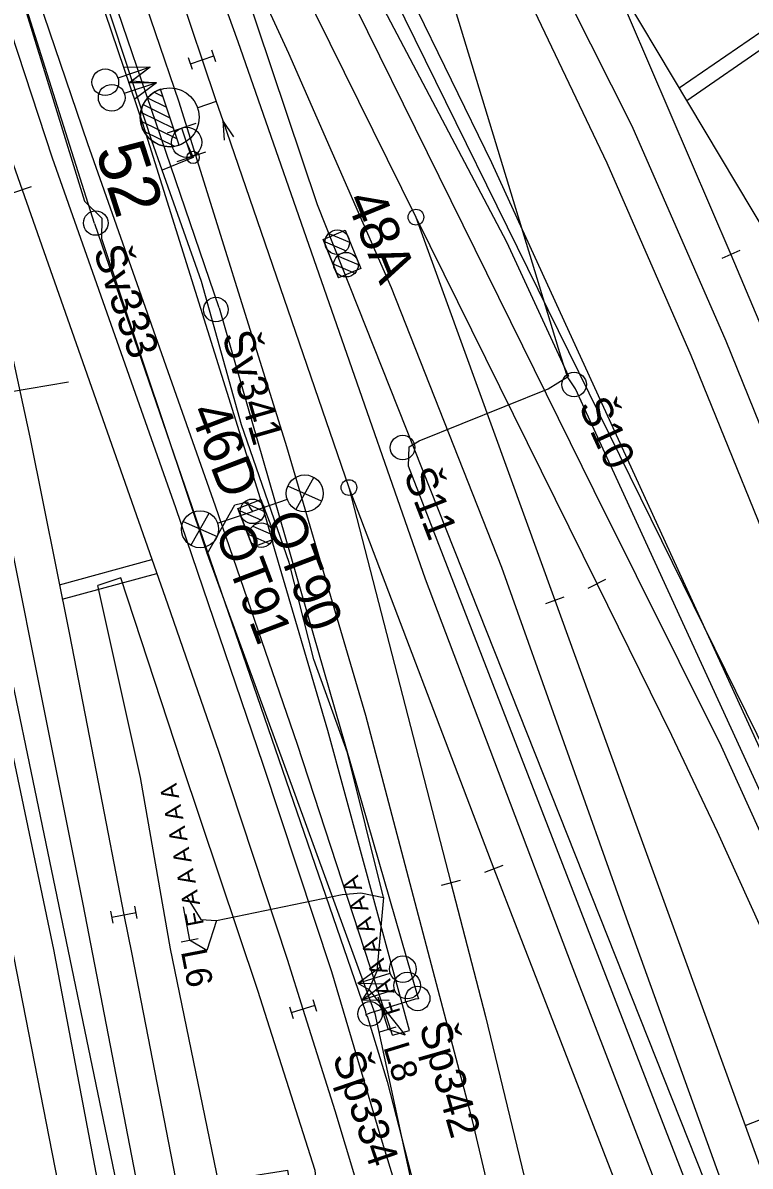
# Model space of a CAD drawing. Extents: x -545736 to -544888, y -1122892 to -1119128.
# Drawn here: x -545209.03 to -545179.41, y -1121691.68 to -1121645.11 of the extents above; entities that cross this region are included whole.
import ezdxf

# ---------------------------------------------------------------- set-up
doc = ezdxf.new("R2010")
doc.units = 0
for name, color, linetype in [('osvětlené plochy-hodnota-obrys', 7, 'Continuous'), ('Vrstva 1 - Koleje', 7, 'Continuous'), ('Vrstva 11 - Trakce', 7, 'Continuous'), ('Vrstva 12 - Trakce zaklady', 7, 'Continuous'), ('Vrstva 2 - Vyhybky', 7, 'Continuous'), ('Vrstva 25', 7, 'Continuous'), ('Vrstva 26', 7, 'Continuous'), ('Vrstva 27', 7, 'Continuous'), ('Vrstva 28 - zabzar', 7, 'Continuous'), ('Vrstva 3 - Lisy - Pocitaci body', 7, 'Continuous'), ('Vrstva 35', 7, 'Continuous'), ('Vrstva 4 - Teren - stezky - prechody - plochy', 7, 'Continuous'), ('Vrstva 43', 7, 'Continuous'), ('Vrstva 44', 7, 'Continuous'), ('Vrstva 6 - Navesti', 7, 'Continuous'), ('Vrstva 7', 7, 'Continuous'), ('Vrstva 7 - Namezniky-vystroj', 7, 'Continuous')]:
    doc.layers.add(name, color=color, linetype=linetype)

msp = doc.modelspace()

# ---------------------------------------------------------------- linework, layer by layer
at = {"layer": 'osvětlené plochy-hodnota-obrys'}
for points in [[(-545137.864, -1121889.42), (-545168.59, -1121731.992), (-545178.308, -1121699.721), (-545197.027, -1121652.528), (-545208.16, -1121619.35), (-545217.952, -1121591.114), (-545225.649, -1121565.547)], [(-545115.194, -1122188.84), (-545115.464, -1122158.52), (-545110.116, -1122078.531), (-545109.516, -1122044.98), (-545111.654, -1121993.485), (-545115.876, -1121955.778), (-545121.955, -1121920.051), (-545160.528, -1121723.806), (-545171.589, -1121690.909), (-545189.933, -1121650.816), (-545214.916, -1121599.46)]]:
    msp.add_lwpolyline(points, dxfattribs=at)
at = {"layer": 'Vrstva 1 - Koleje'}
for points in [[(-545220.059, -1121592.227), (-545219.8, -1121592.995), (-545214.751, -1121607.971), (-545209.438, -1121623.729), (-545206.712, -1121631.824), (-545204.285, -1121639.023), (-545202.147, -1121645.365), (-545201.724, -1121646.618), (-545201.151, -1121648.315)], [(-545225.616, -1121618.075), (-545225.108, -1121619.818), (-545223.546, -1121625.178), (-545221.373, -1121632.649), (-545218.975, -1121641.029), (-545216.466, -1121650.504), (-545215.616, -1121653.926), (-545213.339, -1121663.68), (-545211.292, -1121673.464), (-545209.393, -1121683.199), (-545207.488, -1121692.987)], [(-545219.417, -1121620.337), (-545219.184, -1121621.102), (-545214.573, -1121636.23), (-545210.836, -1121652.388), (-545208.739, -1121661.984), (-545207.134, -1121670.028), (-545205.963, -1121676.033), (-545204.911, -1121681.437), (-545204.598, -1121683.045), (-545202.446, -1121694.084)], [(-545219.417, -1121620.337), (-545219.184, -1121621.102), (-545214.573, -1121636.23), (-545209.054, -1121651.908), (-545206.51, -1121659.176), (-545203.144, -1121668.78), (-545201.044, -1121674.823), (-545198.261, -1121683.246), (-545197.623, -1121685.281), (-545196.328, -1121689.408), (-545194.686, -1121694.87)], [(-545191.612, -1121632.129), (-545190.978, -1121633.194), (-545185.162, -1121642.962), (-545180.201, -1121654.544), (-545176.154, -1121664.128), (-545173.907, -1121669.92), (-545171.157, -1121677.438)], [(-545191.612, -1121632.129), (-545190.978, -1121633.194), (-545185.162, -1121642.962), (-545178.685, -1121653.839)], [(-545200.377, -1121638.127), (-545200.027, -1121638.835), (-545193.022, -1121653.026), (-545187.361, -1121668.627), (-545185.993, -1121672.41), (-545184.116, -1121677.602), (-545182.386, -1121682.379), (-545180.136, -1121688.593), (-545177.412, -1121696.104), (-545175.179, -1121702.365), (-545173.107, -1121708.51), (-545170.943, -1121715.381), (-545168.904, -1121722.322), (-545166.838, -1121730.016), (-545165.721, -1121734.52), (-545165.378, -1121735.902), (-545163.622, -1121743.653), (-545162.109, -1121751.114), (-545160.876, -1121757.439), (-545159.51, -1121764.477), (-545158.293, -1121770.72), (-545156.873, -1121778.046)], [(-545200.377, -1121638.127), (-545200.027, -1121638.835), (-545193.022, -1121653.026), (-545185.653, -1121667.954), (-545182.618, -1121674.124), (-545180.75, -1121678.05), (-545177.273, -1121685.741), (-545175.056, -1121690.975), (-545171.981, -1121698.73), (-545169.454, -1121705.612), (-545167.151, -1121712.394), (-545165.943, -1121716.253), (-545164.96, -1121719.394), (-545162.82, -1121726.889), (-545161.406, -1121732.291), (-545159.388, -1121740.831), (-545157.763, -1121748.706), (-545156.207, -1121756.669), (-545155.623, -1121759.664)], [(-545201.151, -1121648.315), (-545200.885, -1121649.09), (-545195.75, -1121664.039), (-545189.847, -1121679.563), (-545187.972, -1121684.404), (-545185.383, -1121691.101), (-545182.479, -1121698.59)], [(-545201.151, -1121648.315), (-545200.885, -1121649.09), (-545195.75, -1121664.039), (-545191.597, -1121680.133), (-545190.187, -1121685.59), (-545187.923, -1121694.959)]]:
    msp.add_lwpolyline(points, dxfattribs=at)
at = {"layer": 'Vrstva 11 - Trakce'}
for p, q in [((-545196.569, -1121653.691), (-545195.727, -1121654.045)), ((-545196.721, -1121654.033), (-545195.868, -1121654.393)), ((-545196.214, -1121654.605), (-545195.372, -1121654.959)), ((-545196.366, -1121654.947), (-545195.513, -1121655.307)), ((-545200.019, -1121664.643), (-545199.184, -1121665.016)), ((-545200.178, -1121664.982), (-545199.332, -1121665.36)), ((-545199.663, -1121665.612), (-545198.828, -1121665.985)), ((-545199.822, -1121665.951), (-545198.976, -1121666.329))]:
    msp.add_line(p, q, dxfattribs=at)
msp.add_lwpolyline([(-545232.384, -1121664.189), (-545218.403, -1121661.636), (-545207.172, -1121659.74)], dxfattribs=at)
for centre in [(-545196.225, -1121654.048), (-545195.87, -1121654.962), (-545199.682, -1121665.008), (-545199.326, -1121665.977)]:
    msp.add_circle(centre, 0.5, dxfattribs=at)
at = {"layer": 'Vrstva 12 - Trakce zaklady'}
for p, q in [((-545196.805, -1121653.935), (-545195.901, -1121653.556)), ((-545195.267, -1121655.112), (-545196.172, -1121655.494)), ((-545200.274, -1121664.888), (-545199.34, -1121664.531)), ((-545198.734, -1121666.116), (-545199.668, -1121666.473))]:
    msp.add_line(p, q, dxfattribs=at)
for points in [[(-545196.172, -1121655.494), (-545196.805, -1121653.935), (-545195.901, -1121653.556), (-545195.267, -1121655.112), (-545196.172, -1121655.494)], [(-545195.901, -1121653.556), (-545195.901, -1121653.556), (-545195.267, -1121655.112), (-545195.267, -1121655.112)], [(-545196.805, -1121653.935), (-545196.805, -1121653.935), (-545196.172, -1121655.494), (-545196.172, -1121655.494)], [(-545199.668, -1121666.473), (-545200.274, -1121664.888), (-545199.34, -1121664.531), (-545198.734, -1121666.116), (-545199.668, -1121666.473)], [(-545200.274, -1121664.888), (-545200.274, -1121664.888), (-545199.668, -1121666.473), (-545199.668, -1121666.473)], [(-545199.34, -1121664.531), (-545199.34, -1121664.531), (-545198.734, -1121666.116), (-545198.734, -1121666.116)]]:
    msp.add_lwpolyline(points, dxfattribs=at)
at = {"layer": 'Vrstva 2 - Vyhybky'}
for p, q in [((-545203.948, -1121648.167), (-545203.184, -1121648.545)), ((-545203.683, -1121647.941), (-545203.329, -1121648.117)), ((-545202.662, -1121650.092), (-545203.43, -1121647.818)), ((-545204.125, -1121648.437), (-545203.039, -1121648.974)), ((-545201.151, -1121648.315), (-545201.909, -1121648.571)), ((-545204.235, -1121649.097), (-545202.75, -1121649.832)), ((-545204.225, -1121648.745), (-545202.894, -1121649.403)), ((-545204.103, -1121649.519), (-545202.855, -1121650.137)), ((-545209.432, -1121652.04), (-545208.676, -1121651.776)), ((-545179.835, -1121654.384), (-545180.567, -1121654.704)), ((-545186.012, -1121668.131), (-545185.294, -1121667.777)), ((-545187.737, -1121668.763), (-545186.985, -1121668.491)), ((-545190.22, -1121679.707), (-545189.474, -1121679.419)), ((-545191.983, -1121680.238), (-545191.211, -1121680.028))]:
    msp.add_line(p, q, dxfattribs=at)
for points in [[(-545191.612, -1121632.129), (-545190.978, -1121633.194), (-545185.162, -1121642.962), (-545178.685, -1121653.839)], [(-545200.377, -1121638.127), (-545200.027, -1121638.835), (-545193.022, -1121653.026), (-545185.653, -1121667.954)], [(-545185.162, -1121642.962), (-545180.201, -1121654.544)], [(-545201.151, -1121648.315), (-545200.885, -1121649.09), (-545195.75, -1121664.039), (-545189.847, -1121679.563)], [(-545200.438, -1121649.754), (-545200.885, -1121649.09), (-545200.83, -1121649.888)], [(-545193.022, -1121653.026), (-545187.361, -1121668.627)], [(-545195.75, -1121664.039), (-545191.597, -1121680.133)]]:
    msp.add_lwpolyline(points, dxfattribs=at)
for centre, radius in [((-545203.046, -1121648.955), 1.2), ((-545193.022, -1121653.026), 0.32), ((-545195.75, -1121664.039), 0.32)]:
    msp.add_circle(centre, radius, dxfattribs=at)
msp.add_arc((-545203.046, -1121648.955), 1.2, 108.6561, 288.6561, dxfattribs=at)
at = {"layer": 'Vrstva 25'}
for p, q in [((-545196.862, -1121664.588), (-545198.243, -1121663.981)), ((-545197.177, -1121663.623), (-545197.916, -1121664.937)), ((-545198.263, -1121664.521), (-545199.682, -1121665.008)), ((-545202.502, -1121665.428), (-545201.121, -1121666.035)), ((-545202.187, -1121666.393), (-545201.448, -1121665.079)), ((-545201.101, -1121665.495), (-545199.682, -1121665.008))]:
    msp.add_line(p, q, dxfattribs=at)
for centre in [(-545197.549, -1121664.278), (-545201.815, -1121665.738)]:
    msp.add_circle(centre, 0.754, dxfattribs=at)
at = {"layer": 'Vrstva 26'}
for points in [[(-545210.933, -1121634.824), (-545211.323, -1121634.442), (-545211.443, -1121634.176), (-545211.731, -1121634.255), (-545211.919, -1121635.114), (-545211.957, -1121635.419), (-545209.781, -1121641.802), (-545206.521, -1121652.377), (-545205.807, -1121653.061), (-545205.829, -1121653.898), (-545201.519, -1121666.737), (-545200.402, -1121664.748), (-545199.878, -1121664.619), (-545199.803, -1121664.841), (-545199.682, -1121665.008)], [(-545201.519, -1121666.737), (-545194.694, -1121685.456), (-545192.548, -1121695.403), (-545191.089, -1121700.472), (-545190.706, -1121700.096), (-545190.052, -1121700.262)]]:
    msp.add_lwpolyline(points, dxfattribs=at)
at = {"layer": 'Vrstva 27'}
msp.add_line((-545202.092, -1121650.614), (-545202.108, -1121650.566), dxfattribs=at)
msp.add_circle((-545202.1, -1121650.59), 0.25, dxfattribs=at)
at = {"layer": 'Vrstva 28 - zabzar'}
for points in [[(-545194.35, -1121680.74), (-545195.81, -1121674.84), (-545197.18, -1121671.04), (-545198.18, -1121667.09), (-545200.12, -1121661.49), (-545201.75, -1121655.65), (-545203.36, -1121651.11), (-545203.78, -1121649.92), (-545204.58, -1121647.47), (-545205.65, -1121644.21), (-545208.01, -1121637.17), (-545208.1, -1121636.42)], [(-545203.85, -1121646.92), (-545204.58, -1121647.47), (-545203.59, -1121647.55)], [(-545202.36, -1121649.98), (-545202.1, -1121650.59), (-545203.36, -1121651.11)], [(-545202.36, -1121680.69), (-545201.78, -1121681.63), (-545201.15, -1121681.67), (-545201.54, -1121682.9), (-545202.24, -1121682.47)], [(-545201.15, -1121681.67), (-545196.02, -1121680.62), (-545195.27, -1121680.54), (-545194.35, -1121680.74)], [(-545194.35, -1121680.74), (-545194.61, -1121683.74), (-545194.94, -1121684.49), (-545193.46, -1121686.35), (-545194.16, -1121686.11)], [(-545195.39, -1121684.23), (-545194.94, -1121684.49), (-545195.21, -1121684.9)]]:
    msp.add_lwpolyline(points, dxfattribs=at)
at = {"layer": 'Vrstva 3 - Lisy - Pocitaci body'}
for p, q in [((-545201.17, -1121646.695), (-545201.33, -1121646.221)), ((-545202.118, -1121647.015), (-545202.278, -1121646.541)), ((-545202.198, -1121646.778), (-545201.25, -1121646.458)), ((-545203.85, -1121646.92), (-545205.158, -1121647.361)), ((-545203.85, -1121646.92), (-545204.941, -1121646.924)), ((-545203.85, -1121646.92), (-545204.721, -1121647.578)), ((-545203.59, -1121647.55), (-545204.898, -1121647.991)), ((-545203.59, -1121647.55), (-545204.681, -1121647.554)), ((-545203.59, -1121647.55), (-545204.461, -1121648.208)), ((-545203.141, -1121649.594), (-545201.974, -1121649.199)), ((-545202.162, -1121650.563), (-545202.558, -1121649.397)), ((-545202.746, -1121650.761), (-545201.579, -1121650.366)), ((-545204.372, -1121681.587), (-545204.468, -1121681.096)), ((-545205.354, -1121681.778), (-545205.45, -1121681.287)), ((-545205.402, -1121681.533), (-545204.42, -1121681.341)), ((-545195.39, -1121684.23), (-545194.507, -1121683.59)), ((-545195.39, -1121684.23), (-545194.074, -1121683.815)), ((-545195.39, -1121684.23), (-545194.299, -1121684.248)), ((-545195.21, -1121684.9), (-545194.327, -1121684.26)), ((-545195.21, -1121684.9), (-545193.894, -1121684.485)), ((-545197.221, -1121684.893), (-545197.071, -1121685.37)), ((-545195.21, -1121684.9), (-545194.119, -1121684.918)), ((-545198.175, -1121685.192), (-545198.025, -1121685.669)), ((-545197.146, -1121685.131), (-545198.1, -1121685.431))]:
    msp.add_line(p, q, dxfattribs=at)
for centre, radius in [((-545205.672, -1121647.532), 0.542), ((-545205.412, -1121648.162), 0.542), ((-545202.361, -1121649.978), 0.616), ((-545193.556, -1121683.654), 0.542), ((-545193.376, -1121684.324), 0.542)]:
    msp.add_circle(centre, radius, dxfattribs=at)
at = {"layer": 'Vrstva 35'}
msp.add_line((-545201.15, -1121681.67), (-545196.02, -1121680.62), dxfattribs=at)
at = {"layer": 'Vrstva 4 - Teren - stezky - prechody - plochy'}
for points in [[(-545188.763, -1121698.109), (-545190.715, -1121689.813), (-545195.065, -1121673.326), (-545198.286, -1121662.387), (-545202.669, -1121648.347), (-545213.282, -1121617.261), (-545221.968, -1121591.293), (-545228.066, -1121573.381), (-545232.36, -1121560.669), (-545237.333, -1121545.795), (-545240.195, -1121536.787), (-545241.095, -1121537.02)], [(-545191.805, -1121699.137), (-545194.474, -1121690.403), (-545196.452, -1121683.768), (-545199.249, -1121675.317), (-545202.803, -1121664.861), (-545207.816, -1121650.626), (-545217.94, -1121619.813), (-545226.341, -1121592.264), (-545232.146, -1121573.195), (-545235.937, -1121558.858), (-545238.806, -1121546.877), (-545241.095, -1121537.02)], [(-545193.971, -1121686.337), (-545197.84, -1121674.499), (-545201.181, -1121664.796), (-545206.38, -1121650.04), (-545211.277, -1121635.666), (-545211.697, -1121634.349), (-545221.788, -1121601.943), (-545222.646, -1121598.843), (-545224.741, -1121591.802), (-545230.27, -1121573.782), (-545232.734, -1121565.41), (-545232.396, -1121565.328)], [(-545193.971, -1121686.337), (-545193.291, -1121686.158), (-545196.613, -1121673.939), (-545198.848, -1121666.308), (-545198.841, -1121666.311), (-545199.352, -1121664.499), (-545204.149, -1121649.207), (-545214.818, -1121617.793), (-545217.576, -1121610.01), (-545218.122, -1121608.25), (-545223.778, -1121591.338), (-545229.6, -1121573.622), (-545232.396, -1121565.328)], [(-545230.058, -1121593.624), (-545229.255, -1121593.407), (-545223.205, -1121613.276), (-545220.476, -1121622.38), (-545217.216, -1121633.69), (-545214.01, -1121645.83), (-545211.204, -1121657.98), (-545206.59, -1121681.008), (-545202.547, -1121701.925)], [(-545230.058, -1121593.624), (-545227.825, -1121603.756), (-545225.054, -1121614.151), (-545222.526, -1121623.034), (-545219.417, -1121633.474), (-545215.613, -1121647.074), (-545212.994, -1121658.069), (-545207.784, -1121682.857), (-545204.102, -1121702.263)], [(-545216.868, -1121596.848), (-545216.019, -1121596.395), (-545211.21, -1121604.274), (-545206.839, -1121610.949), (-545199.048, -1121622.889), (-545192.587, -1121633.352), (-545188.426, -1121640.975), (-545184.233, -1121649.302), (-545180.4, -1121658.058), (-545176.327, -1121668.124), (-545171.563, -1121681.077), (-545167.703, -1121693.087), (-545168.781, -1121694.447)], [(-545216.868, -1121596.848), (-545213.889, -1121604.829), (-545210.471, -1121613.16), (-545202.274, -1121630.693), (-545185.773, -1121664.159), (-545180.599, -1121674.576), (-545175.283, -1121686.286), (-545171.383, -1121695.992), (-545169.382, -1121701.199), (-545168.755, -1121700.94)], [(-545209.004, -1121612.298), (-545208.216, -1121611.839), (-545200.504, -1121623.754), (-545192.69, -1121636.392), (-545188.479, -1121644.031), (-545185.244, -1121650.818), (-545181.822, -1121658.643), (-545177.576, -1121669.097), (-545173.15, -1121681.254), (-545168.781, -1121694.447)], [(-545209.004, -1121612.298), (-545202.175, -1121627.489), (-545200.979, -1121629.68), (-545184.318, -1121663.578), (-545177.85, -1121676.702), (-545177.318, -1121678.004), (-545173.918, -1121685.556), (-545169.795, -1121695.632), (-545169.981, -1121695.743), (-545169.679, -1121697.265), (-545169.574, -1121697.288), (-545168.755, -1121700.94)], [(-545177.153, -1121708.388), (-545177.337, -1121707.756), (-545186.682, -1121683.465), (-545192.636, -1121667.775), (-545200.255, -1121645.889), (-545203.013, -1121638.235), (-545202.124, -1121637.845)], [(-545177.153, -1121708.388), (-545175.107, -1121707.611), (-545175.507, -1121706.398), (-545184.454, -1121681.584), (-545189.524, -1121667.292), (-545194.023, -1121655.906), (-545198.205, -1121646.356), (-545202.124, -1121637.845)], [(-545200.766, -1121693.77), (-545199.786, -1121693.603), (-545199.971, -1121692.109), (-545198.246, -1121691.849), (-545198.002, -1121693.324), (-545196.981, -1121693.185), (-545197.124, -1121691.857), (-545199.462, -1121684.52), (-545202.574, -1121675.254), (-545205.037, -1121667.713), (-545205.972, -1121668.035)], [(-545200.766, -1121693.77), (-545203.014, -1121682.821), (-545204.237, -1121675.848), (-545205.972, -1121668.035)]]:
    msp.add_lwpolyline(points, dxfattribs=at)
at = {"layer": 'Vrstva 43'}
for centre in [(-545206.06, -1121653.265), (-545201.17, -1121656.791), (-545186.581, -1121659.844), (-545193.566, -1121662.411), (-545192.952, -1121684.849), (-545194.892, -1121685.476)]:
    msp.add_circle(centre, 0.5, dxfattribs=at)
at = {"layer": 'Vrstva 44'}
for points in [[(-545179.583, -1121698.628), (-545193.322, -1121663.167), (-545193.296, -1121662.385), (-545192.894, -1121662.138), (-545187.639, -1121660.012), (-545186.844, -1121659.528), (-545187.117, -1121658.693), (-545194.063, -1121635.912), (-545194.221, -1121635.633), (-545194.492, -1121635.326), (-545208.695, -1121611.436), (-545208.73, -1121611.156), (-545207.976, -1121610.468), (-545202.921, -1121607.01), (-545202.254, -1121606.625), (-545202.44, -1121605.676), (-545215.752, -1121581.308), (-545224.558, -1121560.938)], [(-545201.029, -1121656.72), (-545214.811, -1121616.351), (-545214.861, -1121616.079)], [(-545206.107, -1121653.28), (-545217.409, -1121617.592), (-545217.501, -1121617.32)], [(-545203.565, -1121700.334), (-545212.31, -1121658.192), (-545222.869, -1121618.503), (-545222.832, -1121618.218)], [(-545201.994, -1121629.486), (-545195.239, -1121642.816), (-545189.332, -1121654.028), (-545186.805, -1121659.5), (-545186.844, -1121659.528)], [(-545206.107, -1121653.28), (-545195.07, -1121685.376), (-545195.061, -1121685.517), (-545194.992, -1121685.612), (-545194.193, -1121688.229), (-545191.066, -1121700.374), (-545190.181, -1121705.285), (-545188.159, -1121711.939), (-545183.274, -1121729.753), (-545183.103, -1121729.934)], [(-545201.029, -1121656.72), (-545192.975, -1121684.696), (-545192.917, -1121684.863), (-545193.048, -1121684.88), (-545194.902, -1121685.445), (-545195.061, -1121685.517)], [(-545154.066, -1121755.488), (-545156.631, -1121743.461), (-545160.096, -1121730.567), (-545160.85, -1121728.368), (-545161.141, -1121726.228), (-545163.34, -1121716.222), (-545164.049, -1121714.326), (-545174.37, -1121686.504), (-545186.53, -1121660.015), (-545186.844, -1121659.528)]]:
    msp.add_lwpolyline(points, dxfattribs=at)
at = {"layer": 'Vrstva 6 - Navesti'}
for p, q in [((-545202.505, -1121681.11), (-545202.24, -1121682.47)), ((-545202.584, -1121682.537), (-545201.896, -1121682.403)), ((-545194.572, -1121684.787), (-545194.16, -1121686.11)), ((-545194.494, -1121686.214), (-545193.826, -1121686.006))]:
    msp.add_line(p, q, dxfattribs=at)
at = {"layer": 'Vrstva 7'}
for p, q in [((-545182.301, -1121647.752), (-545178.977, -1121645.471)), ((-545181.994, -1121648.268), (-545178.605, -1121645.944))]:
    msp.add_line(p, q, dxfattribs=at)
at = {"layer": 'Vrstva 7 - Namezniky-vystroj'}
for p, q in [((-545207.54, -1121667.996), (-545203.779, -1121666.967)), ((-545207.422, -1121668.585), (-545203.58, -1121667.535)), ((-545179.617, -1121690.023), (-545176.052, -1121688.623))]:
    msp.add_line(p, q, dxfattribs=at)

# ---------------------------------------------------------------- texts
at = {"layer": 'Vrstva 11 - Trakce'}
for s, rotation, p in [('48A', 292.1687, (-545195.902, -1121652.312)), ('46D', 290.9236, (-545202.26, -1121660.928))]:
    msp.add_text(s, height=1.6, rotation=rotation, dxfattribs=at).set_placement(p)
at = {"layer": 'Vrstva 2 - Vyhybky'}
msp.add_text('52', height=2, rotation=287.8473, dxfattribs=at).set_placement((-545206.089, -1121650.316))
at = {"layer": 'Vrstva 25'}
for s, p in [('OT90', (-545199.139, -1121665.326)), ('OT91', (-545201.216, -1121665.832))]:
    msp.add_text(s, height=1.5, rotation=290.8193, dxfattribs=at).set_placement(p)
at = {"layer": 'Vrstva 43'}
for s, rotation, p in [('Šv333', 288.8659, (-545206.173, -1121654.395)), ('Šv341', 286.0304, (-545200.927, -1121657.837)), ('Š10', 294.6579, (-545186.421, -1121660.701)), ('Š11', 291.1783, (-545193.54, -1121663.499)), ('Šp342', 286.0304, (-545192.902, -1121685.971)), ('Šp334', 288.8659, (-545196.438, -1121687.224))]:
    msp.add_text(s, height=1.25, rotation=rotation, dxfattribs=at).set_placement(p)
at = {"layer": 'Vrstva 6 - Navesti'}
for s, height, rotation, p in [('  F A A A A A A ', 0.7, 101.0403, (-545201.553, -1121682.336)), ('  F A A A A A A ', 0.7, 107.2754, (-545193.492, -1121685.902)), ('L6', 1.05, 281.0121, (-545202.597, -1121682.932)), ('L8', 1.05, 287.0395, (-545194.356, -1121686.826))]:
    msp.add_text(s, height=height, rotation=rotation, dxfattribs=at).set_placement(p)

doc.saveas('drawing.dxf')
